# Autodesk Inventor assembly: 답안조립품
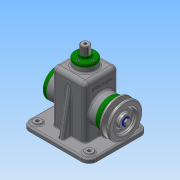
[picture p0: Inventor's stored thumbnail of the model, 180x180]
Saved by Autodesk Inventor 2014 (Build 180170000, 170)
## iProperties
Created: 2015-12
Part Number: 답안조립품
Document SubType Name: Assembly
Designer: Administrator
Author: Administrator
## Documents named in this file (19)
- D:\451225V1003\답안조립품.iam
- D:\451225V1003\1-본체.ipt
- D:\451225V1003\V-벨트풀리.ipt
- D:\451225V1003\고정핀.ipt
- D:\451225V1003\뒤커버.ipt
- D:\451225V1003\링크.ipt
- D:\451225V1003\멈춤링 6 x 5.ipt
- D:\451225V1003\멈춤링 15 x 1.ipt
- D:\451225V1003\베어링 15 x 35 x 11.ipt
- D:\451225V1003\볼트 M3 x 8.ipt
- D:\451225V1003\볼트 M4 x 10.ipt
- D:\451225V1003\볼트 M6 x 12.ipt
- D:\451225V1003\상부부시.ipt
- D:\451225V1003\슬라이드바.ipt
- D:\451225V1003\앞커버.ipt
- D:\451225V1003\오일실 15 25 7.ipt
- D:\451225V1003\와셔.ipt
- D:\451225V1003\키 5 x 5 x 14.ipt
- D:\451225V1003\편심축.ipt
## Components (16 placed, 6 different names)
1. 1-본체:1
2. V-벨트풀리:1 — 플러쉬:2, 각도:2
3. 고정핀:1
4. ISO 4018 M6 x 12:1
5. ISO 4762 M4 x 10:2
6. ISO 4762 M4 x 10:4
7. ISO 4762 M4 x 10:5
8. ISO 4762 M4 x 10:6
9. ISO 4762 M4 x 10:3
10. ISO 4762 M4 x 10:7
11. ISO 4762 M4 x 10:8
12. ISO 4762 M4 x 10:9
13. ISO 4762 M3 x 8:1
14. ISO 4762 M3 x 8:2
15. ISO 4762 M3 x 8:3
16. ISO 4762 M3 x 8:4
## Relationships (2: Flush 1, Angle 1)
- 플러쉬:2 [Flush]: V-벨트풀리:1
- 각도:2 [Angle]: V-벨트풀리:1
